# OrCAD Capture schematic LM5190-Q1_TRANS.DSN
size B; title: LM(2)5190(-Q1) CCCV Buck Converter; rev: 1.0; note: LM5190QEVM-400; note: Synchronous Step Down Converter
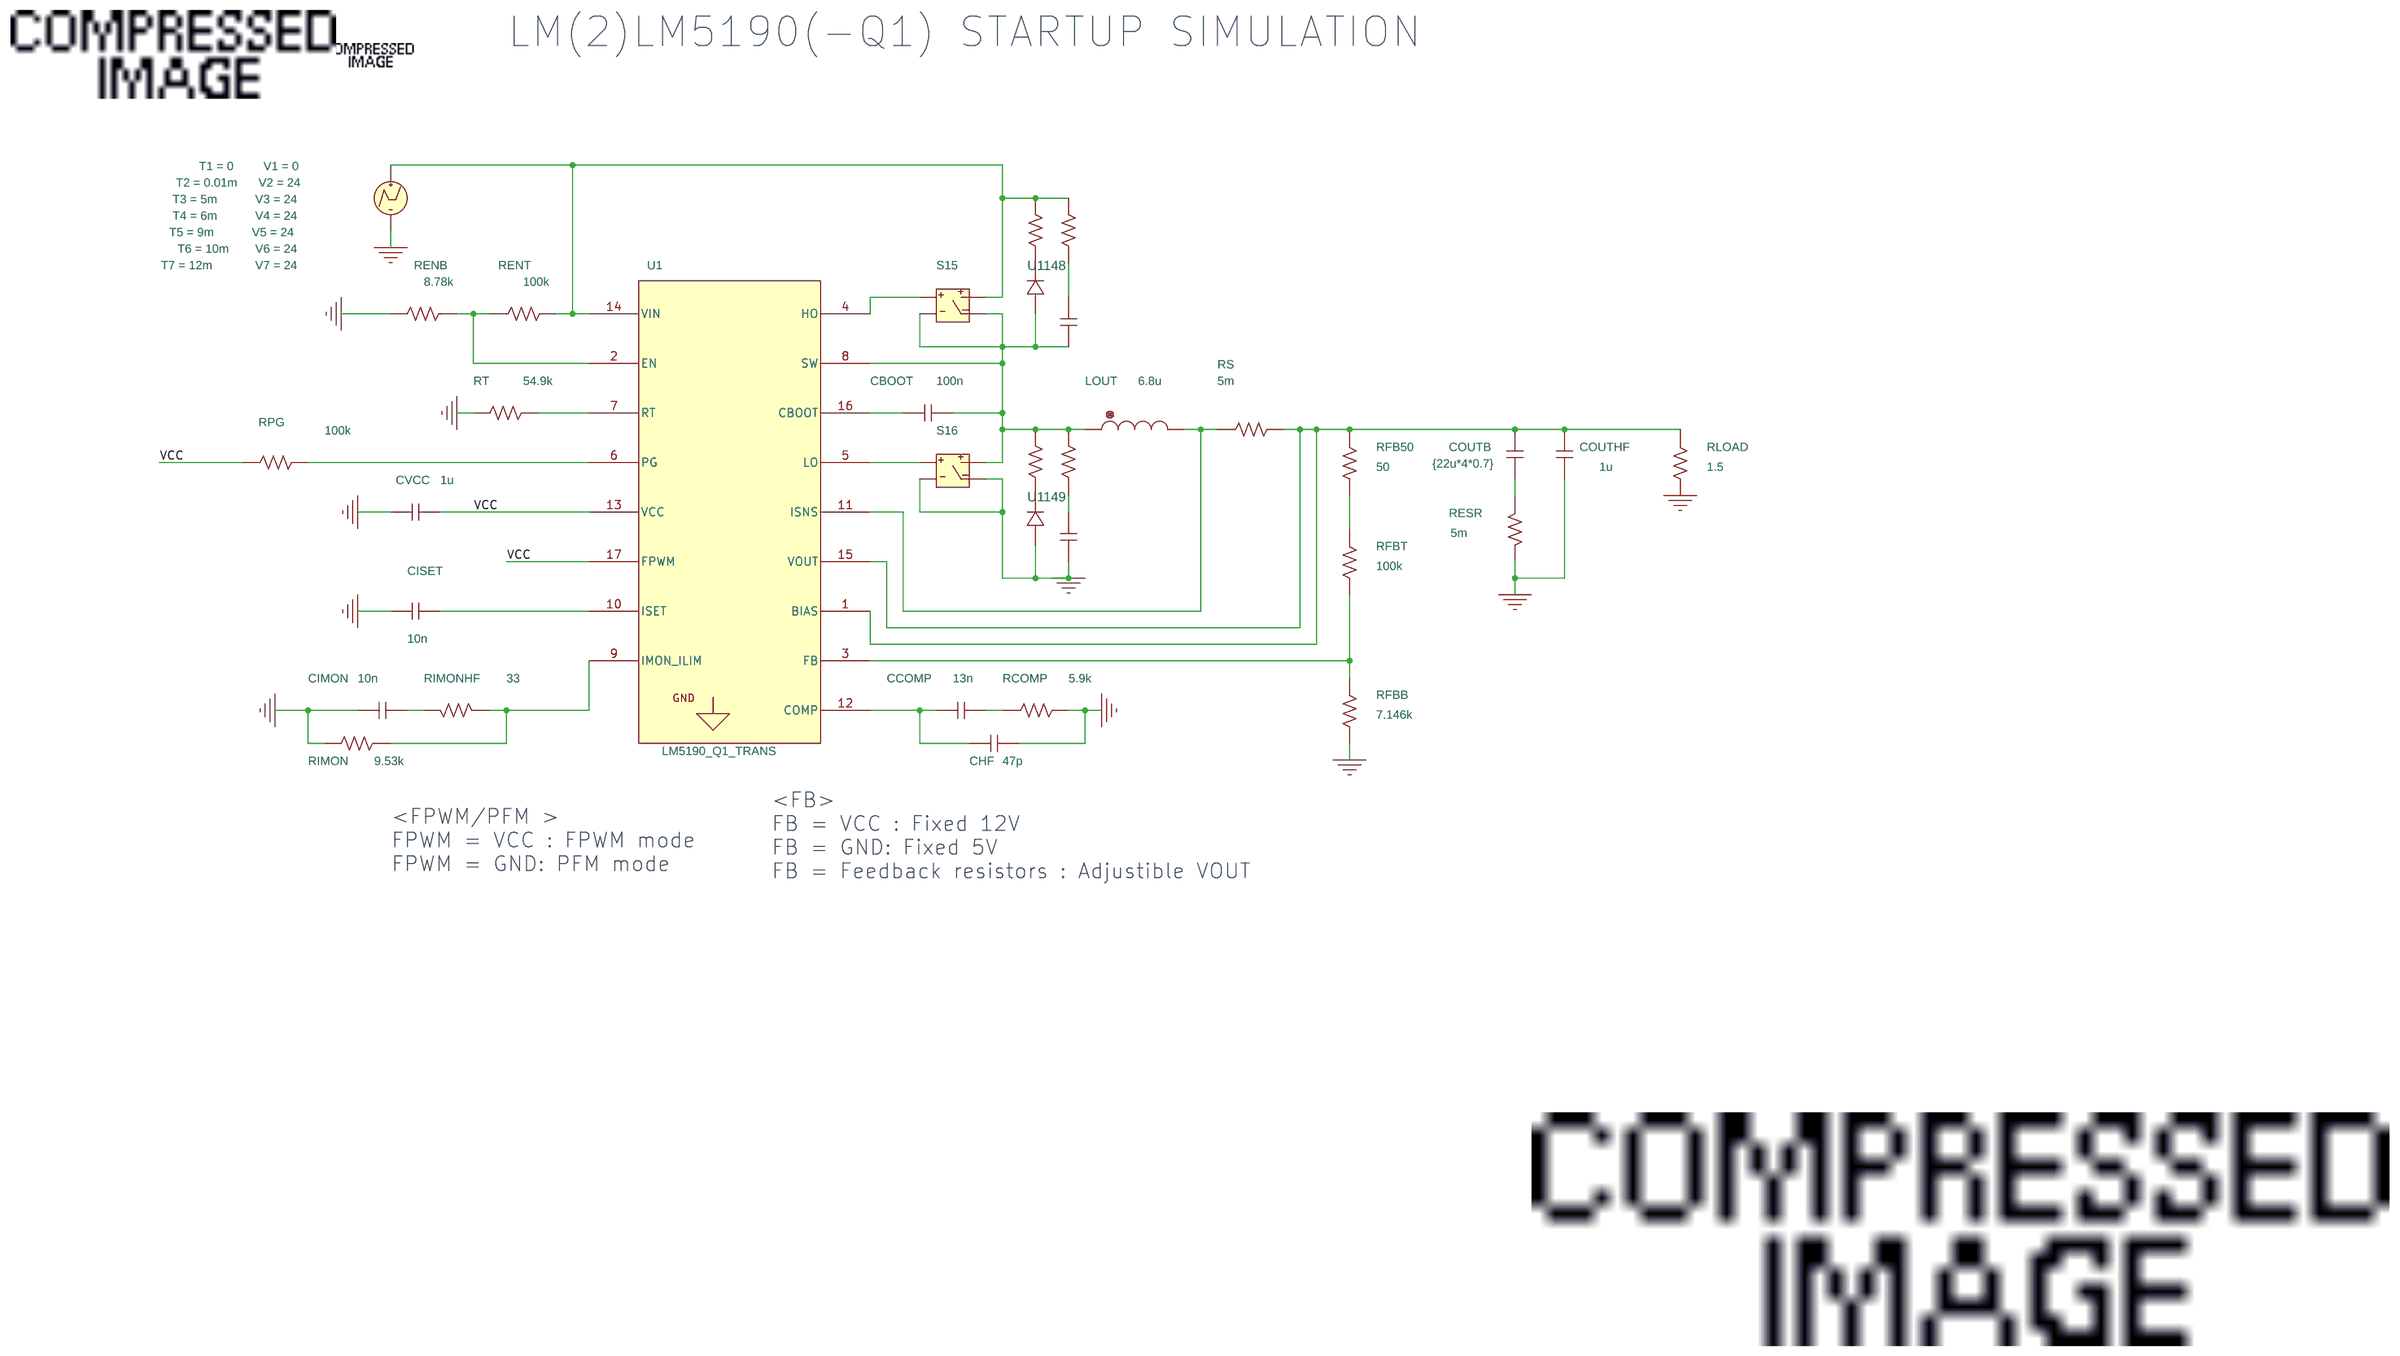
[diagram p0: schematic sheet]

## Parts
C191  200p  [cap196]
C192  400p  [cap196]
CBOOT  100n  [cap196]
CCOMP  13n  [cap196]
CHF  47p  [cap196]
CIMON  10n  [cap196]
CISET  10n  [cap196]
COUTB  {22u*4*0.7}  [cap196]
COUTHF  1u  [cap196]
CVCC  1u  [cap196]
LOUT  6.8u  [DISC350x175LS200x100034]
R306  10m  [AXRC05]
R307  10m  [AXRC05]
R308  5m  [AXRC05]
R309  5m  [AXRC05]
RCOMP  5.9k  [AXRC05]
RENB  8.78k  [AXRC05]
RENT  100k  [AXRC05]
RESR  5m  [AXRC05]
RFB50  50  [AXRC05]
RFBB  7.146k  [AXRC05]
RFBT  100k  [AXRC05]
RIMON  9.53k  [AXRC05]
RIMONHF  33  [AXRC05]
RLOAD  1.5  [AXRC05]
RPG  100k  [AXRC05]
RS  5m  [AXRC05]
RT  54.9k  [AXRC05]
S15  S
S16  S
U1  LM5190_Q1_TRANS
U1148  D_D1
U1149  D_D1
VIN_SUPPLY2  VPWL

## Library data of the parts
C191 C192 CBOOT CCOMP CHF CIMON CISET COUTB COUTHF CVCC = C
LOUT = L
R306-R309 RCOMP RENB RENT RESR RFB50 RFBB RFBT RIMON RIMONHF RLOAD RPG RS RT = R
S15 S16 = S: ROFF: 10Meg; RON: 40m; VOFF: 0.4; VON: 0.6
U1 = LM5190_Q1_TRANS
U1148 U1149 = Dbreak
VIN_SUPPLY2 = VPWL: T1: 0; T2: 0.01m; T3: 5m; T4: 6m; T5: 9m; T6: 10m; T7: 12m; V1: 0; V2: 24; V3: 24; V4: 24; V5: 24; V6: 24; V7: 24

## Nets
VCC: CVCC.2 RPG.1 U1.13(VCC) U1.17(FPWM)
0: C192.1 CHF.1 CIMON.1 CISET.1 COUTHF.1 CVCC.1 RCOMP.2 RENB.2 RESR.2 RFBB.2 RIMON.2 RLOAD.2 RT.2 S16.1(2) S16.3(4) U1149.0(1) VIN_SUPPLY2.2(-)
N16777694: R306.2 R307.2 RENT.2 S15.2(3) U1.14(VIN) VIN_SUPPLY2.1(+)
N16777800: C191.1 CBOOT.1 LOUT.1 R308.2 R309.2 S15.1(2) S15.3(4) S16.2(3) U1.8(SW) U1148.0(1)
N16777840: LOUT.2 RS.1 U1.11(ISNS)
N16777846: COUTB.2 COUTHF.2 RFB50.1 RLOAD.1 RS.2 U1.1(BIAS) U1.15(VOUT)
N16777867: RENB.1 RENT.1 U1.2(EN)
N16777932: COUTB.1 RESR.1
N16778018: RT.1 U1.7(RT)
N16778117: CCOMP.2 CHF.2 U1.12(COMP)
N16778143: CISET.2 U1.10(ISET)
N16778148: RIMON.1 RIMONHF.1 U1.9(IMON_ILIM)
N16778200: CCOMP.1 RCOMP.1
N16778238: CIMON.2 RIMONHF.2
N16779820: RFBB.1 RFBT.2 U1.3(FB)
N16779823: RFB50.2 RFBT.1
N16781211: RPG.2 U1.6(PG)
N16782912: CBOOT.2 U1.16(CBOOT)
N16786599: C191.2 R306.1
N16786672: S15.0(1) U1.4(HO)
N16787257: C192.2 R309.1
N16787459: S16.0(1) U1.5(LO)
N16789940: R308.1 U1149.1(2)
N16789942: R307.1 U1148.1(2)

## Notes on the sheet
- LM(2)LM5190(-Q1) STARTUP SIMULATION
- <FB>
  FB = VCC : Fixed 12V
  FB = GND: Fixed 5V
  FB = Feedback resistors : Adjustible VOUT
- <FPWM/PFM >
  FPWM = VCC : FPWM mode
  FPWM = GND: PFM mode
